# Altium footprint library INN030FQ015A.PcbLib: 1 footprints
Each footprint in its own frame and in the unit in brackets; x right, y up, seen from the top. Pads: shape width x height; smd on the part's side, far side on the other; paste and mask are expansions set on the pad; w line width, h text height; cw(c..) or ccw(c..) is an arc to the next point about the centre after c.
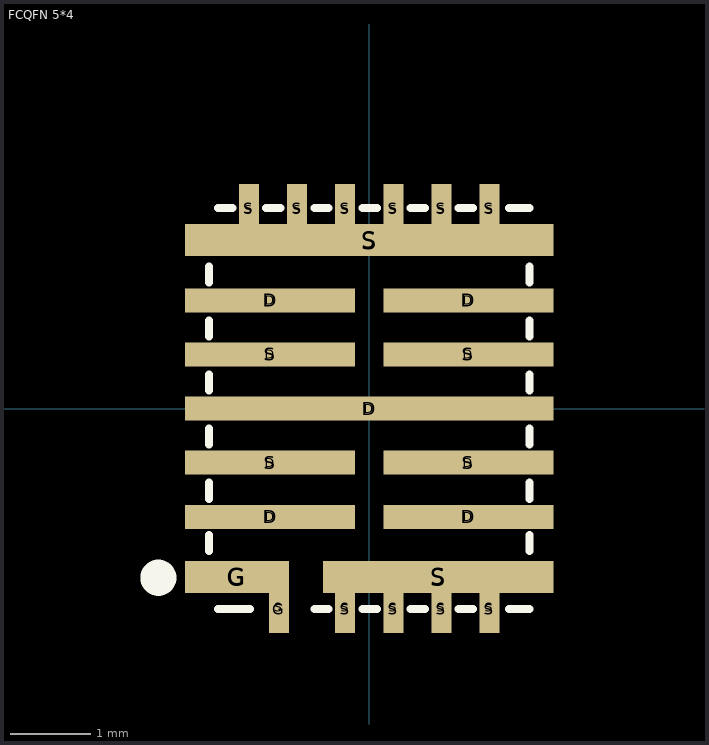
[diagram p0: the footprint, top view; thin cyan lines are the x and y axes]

## FCQFN 5*4 [mm]
pads (46):
  rect 2.085x0.21 on Top Paste paste-1 mask+0.102: D(-1.238,-1.35) D(-1.238,-0.675) D(-1.238,0.675) D(-1.238,1.35) D(1.238,-1.35) D(1.238,-0.675) D(1.238,0.675) D(1.238,1.35)
  rect 2.125x0.3 smd paste-1 mask-0.025: D(-1.238,-1.35) D(-1.238,1.35) D(1.238,-1.35) D(1.238,1.35) S(-1.238,-0.675) S(-1.238,0.675) S(1.238,-0.675) S(1.238,0.675)
  rect 4.56x0.21 on Top Paste paste-1 mask+0.102: D(0,0)
  rect 4.6x0.3 smd paste-1 mask-0.025: D(0,0)
  rect 1.259x0.36 on Top Paste paste-1 mask+0.102: G(-1.651,-2.1)
  rect 1.299x0.4 smd paste-1 mask+0: G(-1.651,-2.1)
  rect 0.25x0.6 smd paste-1 mask+0: G(-1.126,-2.5) S(-1.5,2.5) S(-0.9,2.5) S(-0.3,-2.5) S(-0.3,2.5) S(0.3,-2.5) S(0.3,2.5) S(0.9,-2.5) S(0.9,2.5) S(1.5,-2.5) S(1.5,2.5)
  rect 0.21x0.6 on Top Paste paste-1 mask+0.102: S(-1.5,2.48) S(-1.126,-2.48) S(-0.9,2.48) S(-0.3,-2.48) S(-0.3,2.48) S(0.3,-2.48) S(0.301,2.48) S(0.9,-2.48) S(0.901,2.48) S(1.5,-2.48) S(1.501,2.48)
  rect 4.56x0.36 on Top Paste paste-1 mask+0.102: S(0,2.1)
  rect 4.6x0.4 smd paste-1 mask+0: S(0,2.1)
  rect 2.835x0.36 on Top Paste paste-1 mask+0.102: S(0.863,-2.1)
  rect 2.875x0.4 smd paste-1 mask+0: S(0.863,-2.1)
Top Overlay:
  circle w0.35: c-2.63,-2.11 r0.05
  lines w0.1: -2,-1.775 -2,-1.575 ; -2,-1.125 -2,-0.925 ; -2,-0.45 -2,-0.25 ; -2,0.225 -2,0.425 ; -2,0.9 -2,1.1 ; -2,1.575 -2,1.775 ; -1.885,-2.5 -1.489,-2.5 ; -1.885,2.5 -1.705,2.5 ; -1.285,2.5 -1.105,2.5 ; -0.685,-2.5 -0.505,-2.5 ; -0.685,2.5 -0.505,2.5 ; -0.085,-2.5 0.095,-2.5 ; -0.085,2.5 0.095,2.5 ; 0.515,-2.5 0.695,-2.5 ; 0.515,2.5 0.695,2.5 ; 1.115,-2.5 1.295,-2.5 ; 1.115,2.5 1.295,2.5 ; 1.744,-2.5 2,-2.5 ; 1.744,2.5 2,2.5 ; 2,-1.775 2,-1.575 ; 2,-1.125 2,-0.925 ; 2,-0.45 2,-0.25 ; 2,0.225 2,0.425 ; 2,0.9 2,1.1 ; 2,1.575 2,1.775
3D body "INN040FQ015A FCQFN.STEP": height 0.5, standoff -0.37, extent -2,-2.5 2,2.5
